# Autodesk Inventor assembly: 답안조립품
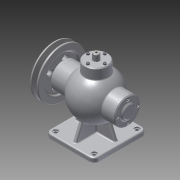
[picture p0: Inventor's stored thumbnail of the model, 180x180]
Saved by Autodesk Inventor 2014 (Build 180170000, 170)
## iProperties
Created: 2017-01
Part Number: 답안조립품
Document SubType Name: Assembly
Designer: ksu
Author: ksu
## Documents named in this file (19)
- C:\Users\ksu\Desktop\답안조립품.iam
- C:\Users\ksu\Desktop\1본체.ipt
- C:\Users\ksu\Desktop\470118V1010\V-벨트풀리.ipt
- C:\Users\ksu\Desktop\470118V1010\너트 M8.ipt
- C:\Users\ksu\Desktop\470118V1010\뒤커버.ipt
- C:\Users\ksu\Desktop\470118V1010\멈춤링- 15 x 1.ipt
- C:\Users\ksu\Desktop\470118V1010\멈춤링- 35x1.6.ipt
- KS B 1336 - 35x1.6.ipt
- C:\Users\ksu\Desktop\470118V1010\베어링- 6202.ipt
- KS B 2023 - 6202 - 15 x 35 x 11 - 7.8.ipt
- C:\Users\ksu\Desktop\470118V1010\볼트 M4 x 12.ipt
- C:\Users\ksu\Desktop\470118V1010\볼트 M4 x 16.ipt
- C:\Users\ksu\Desktop\470118V1010\부시.ipt
- C:\Users\ksu\Desktop\470118V1010\상부커버.ipt
- C:\Users\ksu\Desktop\470118V1010\슬라이드.ipt
- C:\Users\ksu\Desktop\470118V1010\앞커버.ipt
- C:\Users\ksu\Desktop\470118V1010\오일실 15 30 7.ipt
- C:\Users\ksu\Desktop\470118V1010\키 4 x 4 x 12.ipt
- C:\Users\ksu\Desktop\470118V1010\편심축.ipt
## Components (17 placed, 6 different names)
1. 1본체:1 — Mate:1, Mate:13, Mate:14, Mate:15, Mate:16, Mate:21, Mate:22, Mate:23, Mate:26, Mate:27
2. V-벨트풀리:1 — Mate:2, Mate:11, Mate:12
3. KS B 1336 - 35x1.6:1 — Insert:1
4. KS B 2023 - 6202 - 15 x 35 x 11 - 7.8:1 — Mate:3, Mate:7, Mate:20
5. KS B 1021 - 에 따름 ISO 1207 - 미터 A  M 4 x 12:1 — Insert:14
6. ISO 4762 M4 x 16:1 — Insert:3
7. KS B 2023 - 6202 - 15 x 35 x 11 - 7.8:2 — Mate:23, Mate:24, Mate:25, Insert:1, Insert:2
8. ISO 4762 M4 x 16:2 — Insert:4
9. ISO 4762 M4 x 16:3 — Insert:6
10. ISO 4762 M4 x 16:4 — Insert:9
11. ISO 4762 M4 x 16:5 — Insert:10
12. ISO 4762 M4 x 16:6 — Insert:5
13. ISO 4762 M4 x 16:7 — Insert:8
14. ISO 4762 M4 x 16:8 — Insert:7
15. KS B 1021 - 에 따름 ISO 1207 - 미터 A  M 4 x 12:2 — Insert:11
16. KS B 1021 - 에 따름 ISO 1207 - 미터 A  M 4 x 12:3 — Insert:12
17. KS B 1021 - 에 따름 ISO 1207 - 미터 A  M 4 x 12:4 — Insert:13
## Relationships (32: Mate 18, Insert 14)
- Mate:1: 1본체:1
- Mate:2: V-벨트풀리:1
- Mate:3: KS B 2023 - 6202 - 15 x 35 x 11 - 7.8:1
- Mate:7: KS B 2023 - 6202 - 15 x 35 x 11 - 7.8:1
- Mate:11: V-벨트풀리:1
- Mate:12: V-벨트풀리:1
- Mate:13: 1본체:1
- Mate:14: 1본체:1
- Mate:15: 1본체:1
- Mate:16: 1본체:1
- Mate:20: KS B 2023 - 6202 - 15 x 35 x 11 - 7.8:1
- Mate:21: 1본체:1
- Mate:22: 1본체:1
- Mate:23: 1본체:1 ↔ KS B 2023 - 6202 - 15 x 35 x 11 - 7.8:2
- Mate:24: KS B 2023 - 6202 - 15 x 35 x 11 - 7.8:2
- Mate:25: KS B 2023 - 6202 - 15 x 35 x 11 - 7.8:2
- Mate:26: 1본체:1
- Mate:27: 1본체:1
- Insert:1: KS B 1336 - 35x1.6:1 ↔ KS B 2023 - 6202 - 15 x 35 x 11 - 7.8:2
- Insert:2: KS B 2023 - 6202 - 15 x 35 x 11 - 7.8:2
- Insert:3: ISO 4762 M4 x 16:1
- Insert:4: ISO 4762 M4 x 16:2
- Insert:5: ISO 4762 M4 x 16:6
- Insert:6: ISO 4762 M4 x 16:3
- Insert:7: ISO 4762 M4 x 16:8
- Insert:8: ISO 4762 M4 x 16:7
- Insert:9: ISO 4762 M4 x 16:4
- Insert:10: ISO 4762 M4 x 16:5
- Insert:11: KS B 1021 - 에 따름 ISO 1207 - 미터 A  M 4 x 12:2
- Insert:12: KS B 1021 - 에 따름 ISO 1207 - 미터 A  M 4 x 12:3
- Insert:13: KS B 1021 - 에 따름 ISO 1207 - 미터 A  M 4 x 12:4
- Insert:14: KS B 1021 - 에 따름 ISO 1207 - 미터 A  M 4 x 12:1
